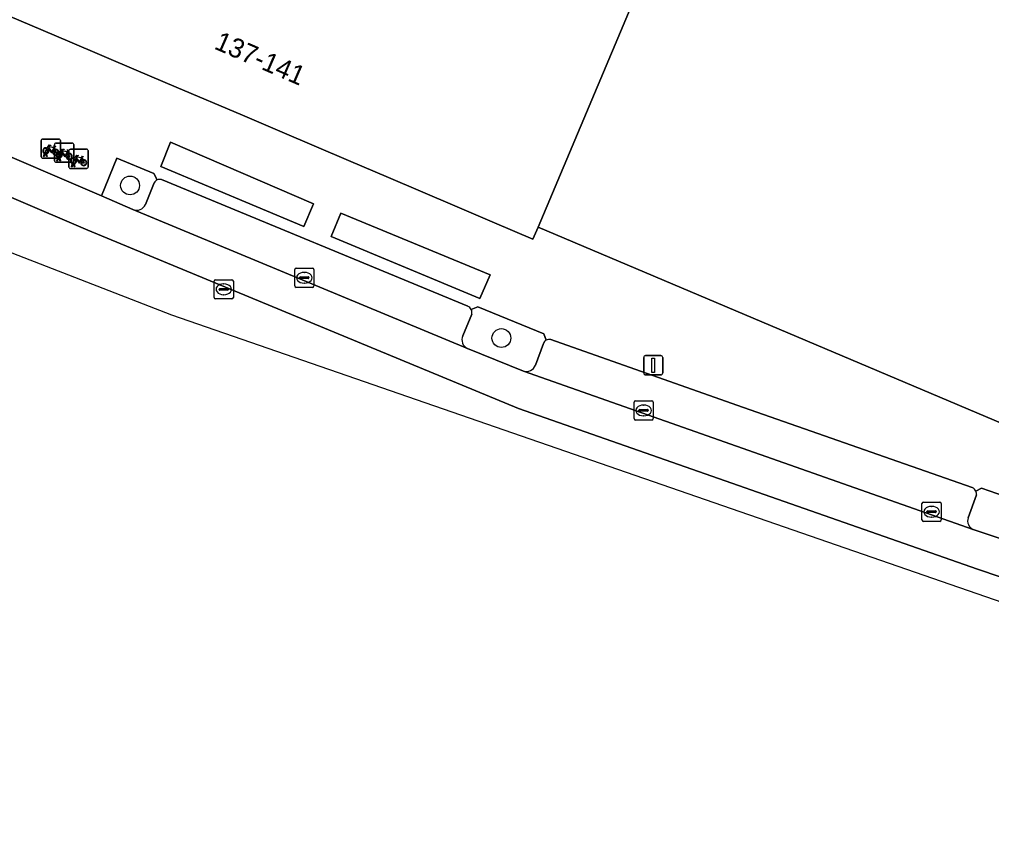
# Model space of a CAD drawing. Extents: x 161771 to 163125, y 382475 to 383179.
# Drawn here: x 162286.2 to 162336.7, y 382568 to 382610.4 of the extents above; entities that cross this region are included whole.
import ezdxf

# ---------------------------------------------------------------- set-up
doc = ezdxf.new("R2010")
doc.units = 0
for name, color, linetype in [('IMGEO_Boom', 7, 'Continuous'), ('IMGEO_Fietsenrek', 7, 'Continuous'), ('IMGEO_Groenvoorziening', 7, 'Continuous'), ('IMGEO_Kolk', 7, 'Continuous'), ('IMGEO_Lichtmast', 7, 'Continuous'), ('IMGEO_Pand', 7, 'Continuous'), ('IMGEO_Pand_nummerreeks', 7, 'Continuous'), ('IMGEO_Parkeervlak_open', 7, 'Continuous'), ('IMGEO_Rijbaan_lokaal_gesloten', 7, 'Continuous'), ('IMGEO_Rijbaan_lokaal_open', 7, 'Continuous'), ('IMGEO_Rioolput', 7, 'Continuous'), ('IMGEO_Voetpad_open', 7, 'Continuous')]:
    doc.layers.add(name, color=color, linetype=linetype)

msp = doc.modelspace()

# ---------------------------------------------------------------- linework, layer by layer
at = {"layer": 'IMGEO_Boom'}
for centre in [(162291.967, 382601.804), (162311.264, 382593.877)]:
    msp.add_circle(centre, 0.489, dxfattribs=at)
at = {"layer": 'IMGEO_Fietsenrek'}
for p, q in [((162287.35, 382603.291), (162287.35, 382604.132)), ((162287.35, 382604.132), (162287.35, 382603.291)), ((162287.425, 382604.216), (162288.266, 382604.216)), ((162288.266, 382604.216), (162287.425, 382604.216)), ((162288.042, 382603.081), (162288.042, 382603.922)), ((162288.042, 382603.922), (162288.042, 382603.081)), ((162288.117, 382604.006), (162288.958, 382604.006)), ((162288.958, 382604.006), (162288.117, 382604.006)), ((162288.35, 382604.141), (162288.35, 382603.3)), ((162288.35, 382603.3), (162288.35, 382604.141)), ((162289.042, 382603.931), (162289.042, 382603.09)), ((162289.042, 382603.09), (162289.042, 382603.931)), ((162287.477, 382603.3), (162287.516, 382603.46)), ((162287.511, 382603.3), (162287.477, 382603.3)), ((162287.546, 382603.448), (162287.511, 382603.3)), ((162287.588, 382603.472), (162287.587, 382603.476)), ((162287.629, 382603.3), (162287.595, 382603.442)), ((162287.619, 382603.483), (162287.62, 382603.476)), ((162287.627, 382603.446), (162287.662, 382603.3)), ((162287.662, 382603.3), (162287.629, 382603.3)), ((162288.037, 382603.765), (162288.073, 382603.67)), ((162288.729, 382603.555), (162288.765, 382603.46)), ((162288.79, 382602.762), (162288.79, 382603.603)), ((162288.79, 382603.603), (162288.79, 382602.762)), ((162288.865, 382603.687), (162289.706, 382603.687)), ((162289.706, 382603.687), (162288.865, 382603.687)), ((162289.79, 382603.612), (162289.79, 382602.771)), ((162289.79, 382602.771), (162289.79, 382603.612)), ((162288.275, 382603.216), (162287.434, 382603.216)), ((162287.434, 382603.216), (162288.275, 382603.216)), ((162288.967, 382603.006), (162288.126, 382603.006)), ((162288.126, 382603.006), (162288.967, 382603.006)), ((162288.169, 382603.09), (162288.208, 382603.25)), ((162288.203, 382603.09), (162288.169, 382603.09)), ((162288.238, 382603.238), (162288.203, 382603.09)), ((162288.28, 382603.262), (162288.279, 382603.266)), ((162288.321, 382603.09), (162288.287, 382603.232)), ((162288.311, 382603.273), (162288.312, 382603.266)), ((162288.319, 382603.236), (162288.354, 382603.09)), ((162288.354, 382603.09), (162288.321, 382603.09)), ((162288.917, 382602.771), (162288.956, 382602.931)), ((162288.951, 382602.771), (162288.917, 382602.771)), ((162288.986, 382602.919), (162288.951, 382602.771)), ((162289.028, 382602.943), (162289.027, 382602.947)), ((162289.069, 382602.771), (162289.035, 382602.913)), ((162289.059, 382602.954), (162289.06, 382602.947)), ((162289.067, 382602.917), (162289.102, 382602.771)), ((162289.102, 382602.771), (162289.069, 382602.771)), ((162289.477, 382603.236), (162289.513, 382603.141)), ((162289.715, 382602.687), (162288.874, 382602.687)), ((162288.874, 382602.687), (162289.715, 382602.687))]:
    msp.add_line(p, q, dxfattribs=at)
for points in [[(162287.663, 382603.742), (162287.758, 382603.906), (162287.844, 382603.892), (162287.846, 382603.883), (162287.79, 382603.872), (162287.763, 382603.827), (162288.019, 382603.786)], [(162288.006, 382603.761), (162287.749, 382603.802), (162287.732, 382603.773), (162287.899, 382603.553), (162288.006, 382603.761)], [(162288.019, 382603.786), (162288.044, 382603.835), (162288.038, 382603.839), (162288.015, 382603.843), (162288.003, 382603.85), (162288.002, 382603.853), (162288.004, 382603.858), (162288.099, 382603.843), (162288.101, 382603.833), (162288.091, 382603.82), (162288.079, 382603.814), (162288.065, 382603.82), (162288.037, 382603.765)], [(162287.684, 382603.69), (162287.632, 382603.6), (162287.592, 382603.575), (162287.593, 382603.622), (162287.648, 382603.716)], [(162287.959, 382603.498), (162287.909, 382603.498), (162287.718, 382603.749), (162287.699, 382603.717)], [(162288.054, 382603.663), (162288.024, 382603.74), (162287.915, 382603.522), (162287.958, 382603.522)], [(162287.988, 382603.522), (162288.108, 382603.521), (162288.064, 382603.635)], [(162288.084, 382603.642), (162288.139, 382603.497), (162287.989, 382603.497)], [(162288.376, 382603.48), (162288.324, 382603.39), (162288.284, 382603.365), (162288.285, 382603.412), (162288.34, 382603.506)], [(162288.355, 382603.532), (162288.45, 382603.696), (162288.536, 382603.682), (162288.538, 382603.673), (162288.482, 382603.662), (162288.455, 382603.617), (162288.711, 382603.576)], [(162288.651, 382603.288), (162288.601, 382603.288), (162288.41, 382603.539), (162288.391, 382603.507)], [(162288.698, 382603.551), (162288.441, 382603.592), (162288.424, 382603.563), (162288.591, 382603.343), (162288.698, 382603.551)], [(162288.746, 382603.453), (162288.716, 382603.53), (162288.607, 382603.312), (162288.65, 382603.312)], [(162288.68, 382603.312), (162288.8, 382603.311), (162288.756, 382603.425)], [(162288.776, 382603.432), (162288.831, 382603.287), (162288.681, 382603.287)], [(162288.711, 382603.576), (162288.736, 382603.625), (162288.73, 382603.629), (162288.707, 382603.633), (162288.695, 382603.64), (162288.694, 382603.643), (162288.696, 382603.648), (162288.791, 382603.633), (162288.793, 382603.623), (162288.783, 382603.61), (162288.771, 382603.604), (162288.757, 382603.61), (162288.729, 382603.555)], [(162289.103, 382603.213), (162289.198, 382603.377), (162289.284, 382603.363), (162289.286, 382603.354), (162289.23, 382603.343), (162289.203, 382603.298), (162289.459, 382603.257)], [(162289.459, 382603.257), (162289.484, 382603.306), (162289.478, 382603.31), (162289.455, 382603.314), (162289.443, 382603.321), (162289.442, 382603.324), (162289.444, 382603.329), (162289.539, 382603.314), (162289.541, 382603.304), (162289.531, 382603.291), (162289.519, 382603.285), (162289.505, 382603.291), (162289.477, 382603.236)], [(162289.124, 382603.161), (162289.072, 382603.071), (162289.032, 382603.046), (162289.033, 382603.093), (162289.088, 382603.187)], [(162289.399, 382602.969), (162289.349, 382602.969), (162289.158, 382603.22), (162289.139, 382603.188)], [(162289.446, 382603.232), (162289.189, 382603.273), (162289.172, 382603.244), (162289.339, 382603.024), (162289.446, 382603.232)], [(162289.494, 382603.134), (162289.464, 382603.211), (162289.355, 382602.993), (162289.398, 382602.993)], [(162289.428, 382602.993), (162289.548, 382602.992), (162289.504, 382603.106)], [(162289.524, 382603.113), (162289.579, 382602.968), (162289.429, 382602.968)]]:
    msp.add_lwpolyline(points, dxfattribs=at)
for centre, radius, start, end in [((162287.428, 382604.138), 0.0779, 92.4484, 184.2845), ((162287.428, 382604.138), 0.0779, 92.4484, 184.2845), ((162288.12, 382603.928), 0.0779, 92.4484, 184.2845), ((162288.12, 382603.928), 0.0779, 92.4484, 184.2845), ((162288.272, 382604.138), 0.0779, 2.4484, 94.2845), ((162288.272, 382604.138), 0.0779, 2.4484, 94.2845), ((162288.964, 382603.928), 0.0779, 2.4484, 94.2845), ((162288.964, 382603.928), 0.0779, 2.4484, 94.2845), ((162287.428, 382603.294), 0.0779, 182.4484, 274.2845), ((162287.428, 382603.294), 0.0779, 182.4484, 274.2845), ((162287.59, 382603.601), 0.159, 62.6766, 242.1369), ((162287.59, 382603.601), 0.129, 63.3192, 238.903), ((162287.57, 382603.472), 0.0499, 12.8025, 158.6934), ((162287.59, 382603.601), 0.159, 253.9967, 271.7867), ((162287.57, 382603.472), 0.0174, 12.8025, 163.4502), ((162287.59, 382603.601), 0.129, 253.415, 269.0204), ((162287.59, 382603.601), 0.129, 283.6043, 43.4302), ((162287.59, 382603.601), 0.159, 283.5766, 46.6042), ((162288.117, 382603.517), 0.159, 113.3408, 178.3217), ((162288.117, 382603.517), 0.159, 187.0065, 105.7708), ((162288.117, 382603.517), 0.129, 113.923, 177.9556), ((162288.117, 382603.517), 0.129, 188.6715, 104.5883), ((162288.282, 382603.391), 0.159, 62.6766, 242.1369), ((162288.282, 382603.391), 0.129, 63.3192, 238.903), ((162288.262, 382603.262), 0.0499, 12.8025, 158.6934), ((162288.262, 382603.262), 0.0174, 12.8025, 163.4502), ((162288.272, 382603.294), 0.0779, 272.4484, 4.2845), ((162288.272, 382603.294), 0.0779, 272.4484, 4.2845), ((162288.282, 382603.391), 0.129, 283.6043, 43.4302), ((162288.282, 382603.391), 0.159, 283.5766, 46.6042), ((162288.809, 382603.307), 0.159, 113.3408, 178.3217), ((162288.809, 382603.307), 0.159, 187.0065, 105.7708), ((162288.809, 382603.307), 0.129, 113.923, 177.9556), ((162288.809, 382603.307), 0.129, 188.6715, 104.5883), ((162288.868, 382603.609), 0.0779, 92.4484, 184.2845), ((162288.868, 382603.609), 0.0779, 92.4484, 184.2845), ((162289.712, 382603.609), 0.0779, 2.4484, 94.2845), ((162289.712, 382603.609), 0.0779, 2.4484, 94.2845), ((162288.12, 382603.084), 0.0779, 182.4484, 274.2845), ((162288.12, 382603.084), 0.0779, 182.4484, 274.2845), ((162288.282, 382603.391), 0.159, 253.9967, 271.7867), ((162288.282, 382603.391), 0.129, 253.415, 269.0204), ((162289.03, 382603.072), 0.159, 62.6766, 242.1369), ((162289.03, 382603.072), 0.129, 63.3192, 238.903), ((162289.01, 382602.943), 0.0499, 12.8025, 158.6934), ((162288.964, 382603.084), 0.0779, 272.4484, 4.2845), ((162288.964, 382603.084), 0.0779, 272.4484, 4.2845), ((162289.03, 382603.072), 0.159, 253.9967, 271.7867), ((162289.01, 382602.943), 0.0174, 12.8025, 163.4502), ((162289.03, 382603.072), 0.129, 253.415, 269.0204), ((162289.03, 382603.072), 0.129, 283.6043, 43.4302), ((162289.03, 382603.072), 0.159, 283.5766, 46.6042), ((162289.557, 382602.988), 0.159, 113.3408, 178.3217), ((162289.557, 382602.988), 0.159, 187.0065, 105.7708), ((162289.557, 382602.988), 0.129, 113.923, 177.9556), ((162289.557, 382602.988), 0.129, 188.6715, 104.5883), ((162289.712, 382602.765), 0.0779, 272.4484, 4.2845), ((162289.712, 382602.765), 0.0779, 272.4484, 4.2845), ((162288.868, 382602.765), 0.0779, 182.4484, 274.2845), ((162288.868, 382602.765), 0.0779, 182.4484, 274.2845)]:
    msp.add_arc(centre, radius, start, end, dxfattribs=at)
at = {"layer": 'IMGEO_Groenvoorziening'}
for points in [[(162301.001, 382599.674), (162301.497, 382600.856), (162294.072, 382604.052), (162293.559, 382602.788)], [(162302.913, 382600.365), (162302.418, 382599.147), (162310.146, 382595.927), (162310.674, 382597.159)]]:
    msp.add_lwpolyline(points, close=True, dxfattribs=at)
for points in [[(162293.379, 382602.094), (162293.199, 382602.424), (162291.279, 382603.215), (162290.489, 382601.256), (162292.11, 382600.553)], [(162292.774, 382600.819), (162293.221, 382601.933)], [(162313.592, 382593.764), (162313.473, 382594.096), (162310.041, 382595.49), (162309.702, 382595.353)], [(162309.725, 382595.123), (162309.258, 382593.996)], [(162309.505, 382593.335), (162312.409, 382592.158)], [(162313.036, 382592.464), (162313.451, 382593.597)], [(162335.962, 382585.724), (162335.516, 382584.532)], [(162335.784, 382583.935), (162337.494, 382583.35), (162338.213, 382585.379), (162336.224, 382586.083), (162335.928, 382585.917)]]:
    msp.add_lwpolyline(points, dxfattribs=at)
for centre, radius, start, end in [((162293.51, 382601.807), 0.315, 114.5801, 156.4975), ((162292.304, 382601.029), 0.514, 247.7872, 335.8751), ((162309.401, 382595.207), 0.335, 345.5005, 25.9207), ((162309.715, 382593.79), 0.501, 155.7676, 245.2114), ((162313.753, 382593.485), 0.321, 119.9535, 159.697), ((162312.554, 382592.655), 0.518, 253.6928, 338.3355), ((162335.594, 382585.759), 0.369, 354.6043, 25.3777), ((162335.988, 382584.385), 0.494, 162.7099, 245.6418)]:
    msp.add_arc(centre, radius, start, end, dxfattribs=at)
at = {"layer": 'IMGEO_Kolk'}
for p, q in [((162300.523, 382596.583), (162300.523, 382597.435)), ((162300.598, 382597.509), (162301.45, 382597.509)), ((162301.011, 382597.289), (162301.036, 382597.289)), ((162301.524, 382597.435), (162301.524, 382596.583)), ((162300.782, 382597.003), (162300.782, 382597.015)), ((162301.22, 382596.966), (162300.822, 382596.966)), ((162300.825, 382597.052), (162301.223, 382597.052)), ((162301.034, 382596.729), (162301.009, 382596.729)), ((162301.266, 382597.015), (162301.266, 382597.003)), ((162301.45, 382596.509), (162300.598, 382596.509)), ((162318.157, 382589.69), (162318.157, 382590.542)), ((162318.232, 382590.616), (162319.084, 382590.616)), ((162318.459, 382590.159), (162318.857, 382590.159)), ((162318.645, 382590.396), (162318.67, 382590.396)), ((162319.158, 382590.542), (162319.158, 382589.69)), ((162318.416, 382590.11), (162318.416, 382590.122)), ((162318.854, 382590.073), (162318.456, 382590.073)), ((162318.668, 382589.836), (162318.643, 382589.836)), ((162318.9, 382590.122), (162318.9, 382590.11)), ((162319.084, 382589.616), (162318.232, 382589.616)), ((162333.123, 382584.425), (162333.123, 382585.277)), ((162333.198, 382585.351), (162334.05, 382585.351)), ((162333.611, 382585.131), (162333.636, 382585.131)), ((162334.124, 382585.277), (162334.124, 382584.425)), ((162333.382, 382584.845), (162333.382, 382584.857)), ((162333.82, 382584.808), (162333.422, 382584.808)), ((162333.425, 382584.894), (162333.823, 382584.894)), ((162333.866, 382584.857), (162333.866, 382584.845)), ((162334.05, 382584.351), (162333.198, 382584.351)), ((162333.634, 382584.571), (162333.609, 382584.571))]:
    msp.add_line(p, q, dxfattribs=at)
for points in [[(162300.523, 382596.583), (162300.523, 382597.435)], [(162300.598, 382597.509), (162301.45, 382597.509)], [(162301.524, 382597.435), (162301.524, 382596.583)], [(162301.45, 382596.509), (162300.598, 382596.509)], [(162318.157, 382589.69), (162318.157, 382590.542)], [(162318.232, 382590.616), (162319.084, 382590.616)], [(162319.158, 382590.542), (162319.158, 382589.69)], [(162319.084, 382589.616), (162318.232, 382589.616)], [(162333.123, 382584.425), (162333.123, 382585.277)], [(162333.198, 382585.351), (162334.05, 382585.351)], [(162334.124, 382585.277), (162334.124, 382584.425)], [(162334.05, 382584.351), (162333.198, 382584.351)]]:
    msp.add_lwpolyline(points, dxfattribs=at)
for centre, radius, start, end in [((162300.6, 382597.433), 0.0765, 91.552, 178.448), ((162300.6, 382597.433), 0.0765, 91.552, 178.448), ((162301.448, 382597.433), 0.0765, 1.552, 88.448), ((162301.448, 382597.433), 0.0765, 1.552, 88.448), ((162300.822, 382597.012), 0.0403, 85.8775, 175.7526), ((162300.819, 382597.002), 0.0366, 178.938, 274.7102), ((162301.223, 382597.009), 0.043, 264.8664, 352.4533), ((162301.227, 382597.014), 0.0386, 1.7309, 96.639), ((162300.6, 382596.585), 0.0765, 181.552, 268.448), ((162300.6, 382596.585), 0.0765, 181.552, 268.448), ((162301.448, 382596.585), 0.0765, 271.552, 358.448), ((162301.448, 382596.585), 0.0765, 271.552, 358.448), ((162318.234, 382590.54), 0.0765, 91.552, 178.448), ((162318.234, 382590.54), 0.0765, 91.552, 178.448), ((162318.456, 382590.119), 0.0403, 85.8775, 175.7526), ((162318.861, 382590.121), 0.0386, 1.7309, 96.639), ((162319.082, 382590.54), 0.0765, 1.552, 88.448), ((162319.082, 382590.54), 0.0765, 1.552, 88.448), ((162318.234, 382589.692), 0.0765, 181.552, 268.448), ((162318.234, 382589.692), 0.0765, 181.552, 268.448), ((162318.453, 382590.109), 0.0366, 178.938, 274.7102), ((162318.857, 382590.116), 0.043, 264.8664, 352.4533), ((162319.082, 382589.692), 0.0765, 271.552, 358.448), ((162319.082, 382589.692), 0.0765, 271.552, 358.448), ((162333.2, 382585.275), 0.0765, 91.552, 178.448), ((162333.2, 382585.275), 0.0765, 91.552, 178.448), ((162334.048, 382585.275), 0.0765, 1.552, 88.448), ((162334.048, 382585.275), 0.0765, 1.552, 88.448), ((162333.422, 382584.854), 0.0403, 85.8775, 175.7526), ((162333.419, 382584.844), 0.0366, 178.938, 274.7102), ((162333.823, 382584.851), 0.043, 264.8664, 352.4533), ((162333.827, 382584.856), 0.0386, 1.7309, 96.639), ((162333.2, 382584.427), 0.0765, 181.552, 268.448), ((162333.2, 382584.427), 0.0765, 181.552, 268.448), ((162334.048, 382584.427), 0.0765, 271.552, 358.448), ((162334.048, 382584.427), 0.0765, 271.552, 358.448)]:
    msp.add_arc(centre, radius, start, end, dxfattribs=at)
for centre, major_axis, ratio, start_param, end_param in [((162301.01, 382597.009), (-0.387, 0.002), 0.722429, 4.712389, 7.853982), ((162301.035, 382597.009), (-0.39, 0.002), 0.717154, 1.570796, 4.712389), ((162318.644, 382590.116), (-0.387, 0.002), 0.722429, 4.712389, 7.853982), ((162318.669, 382590.116), (-0.39, 0.002), 0.717154, 1.570796, 4.712389), ((162333.61, 382584.851), (-0.387, 0.002), 0.722429, 4.712389, 7.853982), ((162333.635, 382584.851), (-0.39, 0.002), 0.717154, 1.570796, 4.712389)]:
    msp.add_ellipse(centre, major_axis=major_axis, ratio=ratio, start_param=start_param, end_param=end_param, dxfattribs=at)
at = {"layer": 'IMGEO_Lichtmast'}
for p, q in [((162318.66, 382592.063), (162318.66, 382592.863)), ((162318.66, 382592.863), (162318.66, 382592.063)), ((162318.76, 382592.963), (162319.55, 382592.963)), ((162319.55, 382592.963), (162318.76, 382592.963)), ((162319.65, 382592.863), (162319.65, 382592.063)), ((162319.65, 382592.063), (162319.65, 382592.863)), ((162319.55, 382591.963), (162318.76, 382591.963)), ((162318.76, 382591.963), (162319.55, 382591.963))]:
    msp.add_line(p, q, dxfattribs=at)
msp.add_lwpolyline([(162319.08, 382592.838), (162319.23, 382592.838), (162319.23, 382592.088), (162319.08, 382592.088), (162319.08, 382592.838)], dxfattribs=at)
for centre, start, end in [((162318.76, 382592.863), 90, 180), ((162318.76, 382592.863), 90, 180), ((162319.55, 382592.863), 0, 90), ((162319.55, 382592.863), 360, 90), ((162318.76, 382592.063), 180, 270), ((162318.76, 382592.063), 180, 270), ((162319.55, 382592.063), 270, 0), ((162319.55, 382592.063), 270, 0)]:
    msp.add_arc(centre, 0.1, start, end, dxfattribs=at)
at = {"layer": 'IMGEO_Pand'}
msp.add_lwpolyline([(162320.101, 382616.097), (162314.228, 382618.615), (162312.143, 382613.751), (162292.459, 382622.19), (162294.111, 382626.044), (162291.175, 382627.303), (162289.511, 382623.447), (162284.254, 382611.213), (162286.762, 382610.146), (162288.83, 382609.267), (162292.279, 382607.8), (162294.365, 382606.912), (162297.808, 382605.447), (162299.876, 382604.565), (162303.325, 382603.093), (162305.395, 382602.21), (162308.846, 382600.737), (162310.913, 382599.855), (162312.902, 382599.006), (162313.172, 382599.641)], close=True, dxfattribs=at)
msp.add_lwpolyline([(162379.028, 382608.247), (162375.863, 382604.377), (162373.376, 382601.335), (162322.929, 382622.738), (162322.058, 382620.699), (162320.101, 382616.097), (162313.172, 382599.641), (162368.466, 382576.233), (162368.518, 382576.348)], dxfattribs=at)
at = {"layer": 'IMGEO_Parkeervlak_open'}
for points in [[(162293.221, 382601.933), (162292.774, 382600.819)], [(162309.513, 382595.526), (162293.596, 382602.109)], [(162292.11, 382600.553), (162309.505, 382593.335)], [(162309.258, 382593.996), (162309.725, 382595.123)], [(162323.501, 382590.382), (162313.828, 382593.798)], [(162313.451, 382593.597), (162313.036, 382592.464)], [(162312.409, 382592.158), (162335.784, 382583.935)], [(162335.732, 382586.104), (162323.501, 382590.382)], [(162335.516, 382584.532), (162335.962, 382585.724)]]:
    msp.add_lwpolyline(points, dxfattribs=at)
for centre, radius, start, end in [((162293.51, 382601.807), 0.315, 114.5801, 156.4975), ((162293.508, 382601.81), 0.312, 73.5663, 114.3422), ((162292.304, 382601.029), 0.514, 247.7872, 335.8751), ((162309.392, 382595.204), 0.343, 25.63, 69.4315), ((162309.401, 382595.207), 0.335, 345.5005, 25.9207), ((162309.715, 382593.79), 0.501, 155.7676, 245.2114), ((162313.753, 382593.485), 0.321, 119.9535, 159.697), ((162313.752, 382593.489), 0.318, 76.1803, 120.2159), ((162312.554, 382592.655), 0.518, 253.6928, 338.3355), ((162335.587, 382585.755), 0.378, 25.3325, 67.3598), ((162335.594, 382585.759), 0.369, 354.6043, 25.3777), ((162335.988, 382584.385), 0.494, 162.7099, 245.6418)]:
    msp.add_arc(centre, radius, start, end, dxfattribs=at)
at = {"layer": 'IMGEO_Rijbaan_lokaal_gesloten'}
for points in [[(162259.358, 382612.5), (162289.771, 382599.475), (162312.157, 382590.208), (162336, 382581.86), (162370.099, 382570.33)], [(162369.708, 382572.396), (162351.179, 382578.613), (162337.494, 382583.35), (162335.784, 382583.935), (162312.409, 382592.158), (162309.505, 382593.335), (162292.11, 382600.553), (162290.489, 382601.256), (162277.062, 382607.009)]]:
    msp.add_lwpolyline(points, dxfattribs=at)
at = {"layer": 'IMGEO_Rijbaan_lokaal_open'}
msp.add_lwpolyline([(162284.329, 382598.88), (162294.125, 382595.073), (162337.774, 382579.977), (162358.532, 382571.685), (162367.821, 382567.975), (162370.099, 382570.33), (162336, 382581.86), (162312.157, 382590.208), (162289.771, 382599.475), (162259.358, 382612.5), (162215.386, 382631.365), (162214.321, 382628.899), (162236.735, 382619.285), (162284.329, 382598.88)], dxfattribs=at)
at = {"layer": 'IMGEO_Rioolput'}
for p, q in [((162296.336, 382595.981), (162296.336, 382596.833)), ((162296.411, 382596.907), (162297.263, 382596.907)), ((162297.337, 382596.833), (162297.337, 382595.981)), ((162296.595, 382596.401), (162296.595, 382596.413)), ((162297.033, 382596.364), (162296.635, 382596.364)), ((162296.638, 382596.45), (162297.036, 382596.45)), ((162296.824, 382596.687), (162296.849, 382596.687)), ((162297.079, 382596.413), (162297.079, 382596.401)), ((162297.263, 382595.907), (162296.411, 382595.907)), ((162296.847, 382596.127), (162296.822, 382596.127))]:
    msp.add_line(p, q, dxfattribs=at)
for points in [[(162296.336, 382595.981), (162296.336, 382596.833)], [(162296.411, 382596.907), (162297.263, 382596.907)], [(162297.337, 382596.833), (162297.337, 382595.981)], [(162297.263, 382595.907), (162296.411, 382595.907)]]:
    msp.add_lwpolyline(points, dxfattribs=at)
for centre, radius, start, end in [((162296.413, 382596.831), 0.0765, 91.552, 178.448), ((162296.413, 382596.831), 0.0765, 91.552, 178.448), ((162297.261, 382596.831), 0.0765, 1.552, 88.448), ((162297.261, 382596.831), 0.0765, 1.552, 88.448), ((162296.635, 382596.41), 0.0403, 85.8775, 175.7526), ((162296.632, 382596.4), 0.0366, 178.938, 274.7102), ((162297.036, 382596.407), 0.043, 264.8664, 352.4533), ((162297.04, 382596.412), 0.0386, 1.7309, 96.639), ((162296.413, 382595.983), 0.0765, 181.552, 268.448), ((162296.413, 382595.983), 0.0765, 181.552, 268.448), ((162297.261, 382595.983), 0.0765, 271.552, 358.448), ((162297.261, 382595.983), 0.0765, 271.552, 358.448)]:
    msp.add_arc(centre, radius, start, end, dxfattribs=at)
for centre, major_axis, ratio, start_param, end_param in [((162296.823, 382596.407), (-0.387, 0.002), 0.722429, 4.712389, 7.853982), ((162296.848, 382596.407), (-0.39, 0.002), 0.717154, 1.570796, 4.712389)]:
    msp.add_ellipse(centre, major_axis=major_axis, ratio=ratio, start_param=start_param, end_param=end_param, dxfattribs=at)
at = {"layer": 'IMGEO_Voetpad_open'}
for points in [[(162294.365, 382606.912), (162292.279, 382607.8), (162288.83, 382609.267), (162286.762, 382610.146), (162284.254, 382611.213), (162283.306, 382611.617), (162281.236, 382612.499), (162280.2, 382612.94), (162278.852, 382613.51), (162272.483, 382616.202), (162265.952, 382618.963), (162263.483, 382620.093), (162258.238, 382622.35), (162253.244, 382624.498), (162252.373, 382624.853), (162247.257, 382627.071), (162241.457, 382629.541), (162235.937, 382631.893), (162230.555, 382634.184), (162224.667, 382636.684), (162218.779, 382639.183), (162215.471, 382640.922)], [(162277.062, 382607.009), (162290.489, 382601.256), (162291.279, 382603.215), (162293.199, 382602.424), (162293.379, 382602.094)], [(162368.518, 382576.348), (162368.466, 382576.233), (162313.172, 382599.641), (162312.902, 382599.006), (162310.913, 382599.855), (162308.846, 382600.737), (162305.395, 382602.21), (162303.325, 382603.093), (162299.876, 382604.565), (162297.808, 382605.447), (162294.365, 382606.912)], [(162293.596, 382602.109), (162309.513, 382595.526)], [(162309.702, 382595.353), (162310.041, 382595.49), (162313.473, 382594.096), (162313.592, 382593.764)], [(162313.828, 382593.798), (162323.501, 382590.382), (162335.732, 382586.104)], [(162335.928, 382585.917), (162336.224, 382586.083), (162338.213, 382585.379), (162337.494, 382583.35), (162351.179, 382578.613), (162369.708, 382572.396), (162369.783, 382572.369), (162373.915, 382577.575), (162373.796, 382577.669)]]:
    msp.add_lwpolyline(points, dxfattribs=at)
for points in [[(162301.001, 382599.674), (162293.559, 382602.788), (162294.072, 382604.052), (162301.497, 382600.856)], [(162302.913, 382600.365), (162310.674, 382597.159), (162310.146, 382595.927), (162302.418, 382599.147)]]:
    msp.add_lwpolyline(points, close=True, dxfattribs=at)
for centre, radius, start, end in [((162293.508, 382601.81), 0.312, 73.5663, 114.3422), ((162309.392, 382595.204), 0.343, 25.63, 69.4315), ((162313.752, 382593.489), 0.318, 76.1803, 120.2159), ((162335.587, 382585.755), 0.378, 25.3325, 67.3598)]:
    msp.add_arc(centre, radius, start, end, dxfattribs=at)

# ---------------------------------------------------------------- texts
at = {"layer": 'IMGEO_Pand_nummerreeks'}
msp.add_text('137-141', height=1, rotation=336.5488, dxfattribs=at).set_placement((162296.286, 382608.927))

doc.saveas('drawing.dxf')
